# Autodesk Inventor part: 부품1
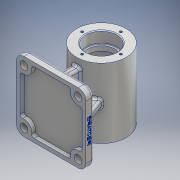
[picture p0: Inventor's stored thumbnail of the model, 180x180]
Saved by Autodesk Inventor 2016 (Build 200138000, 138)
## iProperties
Created: 2019-06
Part Number: 부품1
Material: 알루미늄 6061
Document SubType Name: Modeling
Designer: 605-12
Density: 2.7 g/cm^3
Appearance: 알루미늄 - 평지
Mass: 609.113 g
Surface Area: 624.232 cm^2
Volume: 225.597 cm^3
Author: 605-12
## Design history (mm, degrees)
sketch "스케치1"
  geometry: C1 r 32 at (0, 0); 1 further point
  constraints: 1 centre point, 1 coincident
  dimensions: "d0" = 64 diameter of C1
extrude "돌출1" new body sketch "스케치1" distance "d1" = 90; taper "d2" = 0 deg
sketch "스케치2"
  geometry: C1 r 32 at (0, 0) reference; C2 r 20 at (0, 0); 1 further point
  constraints: 1 centre point, 1 coincident
  dimensions: "d3" = 40 diameter of C2
extrude "돌출2" cut sketch "스케치2" distance "d4" = 15; taper "d5" = 0 deg
sketch "스케치3"
  geometry: C1 r 20 at (0, 0) reference; C2 r 32 at (0, 0) reference; C3 r 17 at (0, 0); 1 further point
  constraints: 1 centre point, 1 coincident
  dimensions: "d6" = 34 diameter of C3
extrude "돌출3" cut sketch "스케치3" distance "d7" = 6; taper "d8" = 0 deg
sketch "스케치4"
  geometry: C1 r 17 at (0, 0) reference; C2 r 32 at (0, 0) reference; C3 r 25 at (0, 0); 1 further point
  constraints: 1 centre point, 1 coincident
  dimensions: "d9" = 50 diameter of C3
extrude "돌출4" cut sketch "스케치4" distance "d10" = 48; taper "d11" = 0 deg
sketch "스케치5"
  geometry: L1 (0, 0)-(0, 37.484); C1 r 25 at (0, 0); 3 further points
  constraints: 2 end point, 1 centre point, 1 coincident, 1 point on line, 1 vertical, 1 vertical alignment, 1 other
  dimensions: "d12" = 50 diameter of C1
hole "구멍1" sketch "스케치5" at (0, 25) diameter "d13" = 3.242; stored, may be unused: countersink angle "d17" = 90 deg, drill point angle "d19" = 118 deg; dims "d14" = 7, "d15" = 4, "d16" = 2, "d18" = 9
node "작업 평면1"
node "작업 평면2"
sketch "스케치6"
  geometry: L1 (-32, -90)-(32, -90) reference; L2 (32, 0)-(32, -90) reference; L3 (-32, 0)-(-32, -90) reference; L4 (45, 0)-(-45, 0); L5 (-45, 0)-(-45, -90); L6 (-45, -90)-(45, -90) reference; L7 (45, -90)-(45, 0) reference; L8 (45, 0)-(-45, -90); L9 (-45, 0)-(45, -90); 2 further points
  constraints: 12 end point, 2 horizontal, 2 midpoint, 2 parallel, 1 perpendicular, 1 vertical
  dimensions: "d24" = 90 distance of L6.end L5.end; "d25" = 90 distance of L5.end L4.end
extrude "돌출5" join sketch "스케치6" distance "d26" = 10; taper "d27" = 0 deg
sketch "스케치7"
  geometry: L1 (32, 0)-(32, -90) reference; L2 (32, -90)-(26.621, -90) reference; L3 (26.621, -90)-(26.621, -81) reference; L4 (26.621, -81)-(25, -80.026) reference; L5 (25, -80.026)-(23.379, -81) reference; L6 (23.379, -81)-(23.379, -90) reference; L7 (23.379, -90)-(20, -90) reference; L8 (20, -90)-(20, -75) reference; L9 (20, -75)-(17, -75) reference; L10 (17, -75)-(17, -69) reference; L11 (17, -69)-(25, -69) reference; L12 (25, -69)-(25, -21) reference; L13 (25, -21)-(17, -21) reference; L14 (17, -21)-(17, -15) reference; L15 (17, -15)-(20, -15) reference; L16 (20, -15)-(20, 0) reference; L17 (20, 0)-(23.379, 0) reference; L18 (23.379, 0)-(23.379, -9) reference; L19 (23.379, -9)-(25, -9.974) reference; L20 (25, -9.974)-(26.621, -9) reference; L21 (26.621, -9)-(26.621, 0) reference; L22 (26.621, 0)-(32, 0) reference; L23 (-32, -90)-(-32, 0) reference; L24 (-32, 0)-(-26.621, 0) reference; L25 (-26.621, 0)-(-26.621, -9) reference; L26 (-26.621, -9)-(-25, -9.974) reference; L27 (-25, -9.974)-(-23.379, -9) reference; L28 (-23.379, -9)-(-23.379, 0) reference; L29 (-23.379, 0)-(-20, 0) reference; L30 (-20, 0)-(-20, -15) reference; L31 (-20, -15)-(-17, -15) reference; L32 (-17, -15)-(-17, -21) reference; L33 (-17, -21)-(-25, -21) reference; L34 (-25, -21)-(-25, -69) reference; L35 (-25, -69)-(-17, -69) reference; L36 (-17, -69)-(-17, -75) reference; L37 (-17, -75)-(-20, -75) reference; L38 (-20, -75)-(-20, -90) reference; L39 (-20, -90)-(-23.379, -90) reference; L40 (-23.379, -90)-(-23.379, -81) reference; L41 (-23.379, -81)-(-25, -80.026) reference; L42 (-25, -80.026)-(-26.621, -81) reference; L43 (-26.621, -81)-(-26.621, -90) reference; L44 (-26.621, -90)-(-32, -90) reference; L45 (-65, 0)-(-55, 0) reference; L46 (-55, 0)-(-55, -90) reference; L47 (-55, -90)-(-65, -90) reference; L48 (-65, -90)-(-65, 0) reference; L49 (32, 0)-(32, -90) reference; L50 (-65, -90)-(-65, 0) reference; L51 (-29.31, -10)-(-29.31, -80) reference; L52 (-29.31, -10)-(-55, -10) reference; L53 (-29.31, -80)-(-55, -80) reference; L54 (-55, -90)-(-55, 0) reference; L55 (-55, -10)-(-55, -80); 1 further point
  constraints: 8 end point, 2 horizontal, 2 point on line, 1 perpendicular, 1 vertical
extrude "돌출6" join sketch "스케치7" stored distance "d30" = 10; taper "d31" = 0 deg
node "작업 평면3"
sketch "스케치8"
  geometry: L1 (45, -55)-(45, -65) reference; L2 (45, -65)-(-45, -65) reference; L3 (-45, -65)-(-45, -55) reference; L4 (-45, -55)-(-5, -55) reference; L5 (-5, -55)-(-5, -31.607) reference; L6 (5, -31.607)-(5, -55) reference; L7 (5, -55)-(45, -55) reference; L8 (-35, -54.99)-(-23.06, -22.186); C1 r 25 at (0, 0) reference; A1 r 32 centre (0, 0) between (5, -31.607) and (-5, -31.607) reference; 1 further point
  constraints: 2 end point, 1 point on circle
feature "리브1" sketch "스케치8" dims "d35" = 1, "d36" = 10, "d37" = 0, "d38" = 0, "d39" = 1, "d40" = 1
node "작업 평면4"
node "작업 평면5"
sketch "스케치9"
  geometry: L1 (-32, -90)-(32, -90) reference; L2 (0, -90)-(0, 0); L3 (-32, 0)-(-32, -90) reference; L4 (-32, -45)-(32, -45); L5 (32, 0)-(32, -90) reference; C1 r 5 at (0, -45)
  constraints: 4 end point, 4 midpoint, 1 centre point, 1 vertical
  dimensions: "d42" = 10 diameter of C1
extrude "돌출7" join sketch "스케치9" stored distance "d43" = 10; taper "d44" = 0 deg
sketch "스케치10"
  geometry: C1 r 5 at (0, 0) reference; 2 further points
  constraints: 1 coincident
hole "구멍2" sketch "스케치10" at (0, 0) diameter "d45" = 4.917; stored, may be unused: countersink angle "d49" = 90 deg, drill point angle "d51" = 118 deg; dims "d46" = 17, "d47" = 4, "d48" = 2, "d50" = 22.1
sketch "스케치11"
  geometry: L1 (-45, 0)-(-45, 90) reference; L2 (-45, 90)-(45, 90) reference; L3 (45, 90)-(45, 0) reference; L4 (45, 0)-(-45, 0) reference; L5 (-5, 40)-(-35.004, 40) reference; L6 (-35.004, 40)-(-35.004, 50) reference; L7 (-35.004, 50)-(-5, 50) reference; L8 (-5, 50)-(-5, 80) reference; L9 (-5, 80)-(5, 80) reference; L10 (5, 80)-(5, 50) reference; L11 (5, 50)-(35.004, 50) reference; L12 (35.004, 50)-(35.004, 40) reference; L13 (35.004, 40)-(5, 40) reference; L14 (5, 40)-(5, 10) reference; L15 (5, 10)-(-5, 10) reference; L16 (-5, 10)-(-5, 40) reference; C1 r 5 at (-35, 80) reference; 1 further point
  constraints: 1 centre point, 1 other
extrude "돌출8" cut sketch "스케치11" distance "d55" = 10; taper "d56" = 0 deg
sketch "스케치12"
  geometry: L1 (-45, -90)-(-45, 0) reference; L2 (-45, 0)-(45, 0) reference; L3 (45, 0)-(45, -90) reference; L4 (45, -90)-(-45, -90) reference; L5 (45, 0)-(45, -90) reference; L6 (-45, -90)-(-45, 0) reference; L7 (-32, -90)-(32, -90) reference; L8 (-40, -85)-(40, -5); L9 (40, -85)-(-40, -5); L10 (26.34, -5)-(-26.34, -5) reference; L11 (40, -71.34)-(40, -18.66) reference; L12 (-40, -18.66)-(-40, -71.34) reference; L13 (-26.34, -85)-(26.34, -85) reference; C1 r 5 at (35, -10) reference; C2 r 5 at (35, -80) reference; C3 r 5 at (-35, -10) reference; C4 r 5 at (-35, -80) reference; A1 r 10 centre (35, -10) between (26.34, -5) and (40, -18.66); A2 r 10 centre (35, -80) between (40, -71.34) and (26.34, -85); A3 r 10 centre (-35, -80) between (-26.34, -85) and (-40, -71.34) reference; A4 r 10 centre (-35, -10) between (-40, -18.66) and (-26.34, -5) reference; 2 further points
  constraints: 12 end point, 8 point on circle, 4 centre point, 4 coincident, 3 horizontal, 2 midpoint, 2 parallel, 2 vertical, 1 perpendicular, 2 other
  dimensions: "d65" = 20 diameter of A1; "d66" = 20 diameter of A2
extrude "돌출9" cut sketch "스케치12" distance "d69" = 5; taper "d70" = 0 deg
fillet "모깎기1" dims "d71" = 3
fillet "모깎기2" dims "d72" = 10
fillet "모깎기3" dims "d73" = 2
fillet "모깎기4" dims "d74" = 3
fillet "모깎기5" dims "d75" = 0.6
fillet "모깎기6" dims "d76" = 3
fillet "모깎기7" dims "d77" = 3
fillet "모깎기8" dims "d78" = 3
sketch "스케치13"
  geometry: L1 (0, 0)-(-10, 0) reference; L2 (-10, 7)-(-10, 0) reference; 2 further points
  constraints: 1 other
  dimensions: "d79" = 4 distance from line of L1 point (35, 4); "d80" = 45 distance from line of point (35, 4) L2
feature "엠보싱1" sketch "스케치13" dims "d0" = 64, "d9" = 50, "d81" = 0.5, "d82" = 0
chamfer "모따기1" distance "d83" = 1; stored, may be unused: second distance "d84" = 2, angle "d85" = 45 deg
node "솔리드1"
pattern_circular "원형 패턴1" dims angle "d21" = 360 deg
mirror "대칭1"
mirror "대칭2"
pattern_linear "직사각형 패턴1" dims "d59" = 70
node "절단 모서리 투영1"
node "절단 모서리 투영2"
node "절단 모서리 투영3"
node "절단 모서리 투영4"
node "절단 모서리 투영5"
node "절단 모서리 투영6"
node "절단 모서리 투영7"
node "절단 모서리 투영8"
other parameters: "d23" = -65, "d28" = 35, "d29" = 35, "d32" = -45, "d34" = 110 deg
